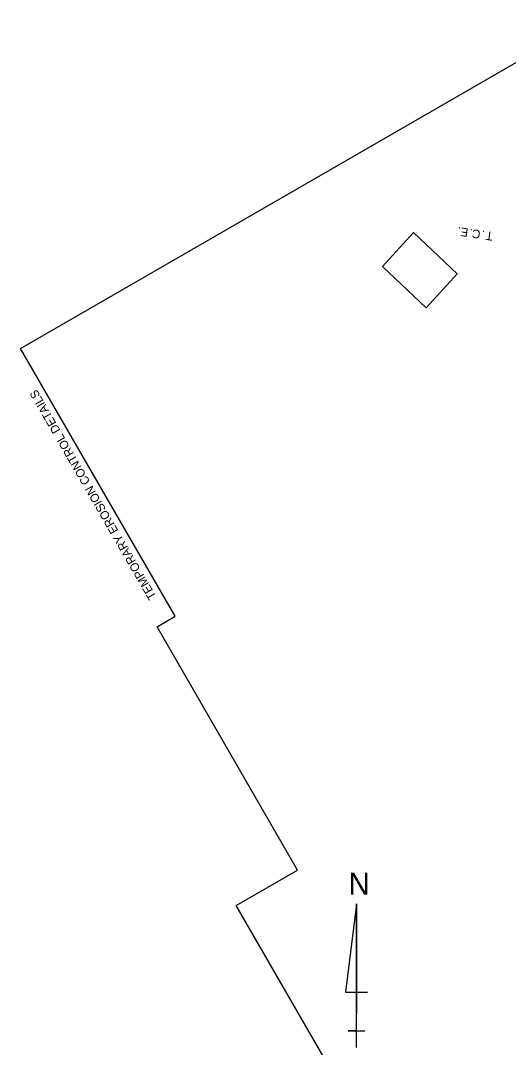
# Model space of a CAD drawing. Extents: x 956270 to 957915, y 1920230 to 1922423.
# Drawn here: x 956270 to 956610, y 1921447 to 1922163 of the extents above; entities that cross this region are included whole.
import ezdxf

# ---------------------------------------------------------------- set-up
doc = ezdxf.new("R2010")
doc.units = 0
for name, color, linetype in [('1', 7, 'Continuous'), ('63', 7, 'Continuous'), ('NO PLOT', 7, 'Continuous'), ('R_Draft', 7, 'Continuous')]:
    doc.layers.add(name, color=color, linetype=linetype)

msp = doc.modelspace()

# ---------------------------------------------------------------- linework, layer by layer
at = {"layer": '63'}
for p, q in [((956504.33, 1921547.02), (956496.64, 1921485.48)), ((956504.33, 1921447.02), (956504.33, 1921547.02)), ((956504.33, 1921547.02), (956504.33, 1921470.09)), ((956496.64, 1921485.48), (956512.03, 1921485.48)), ((956504.33, 1921447.02), (956504.33, 1921470.09)), ((956504.33, 1921458.55), (956498.57, 1921458.55)), ((956498.57, 1921458.55), (956510.1, 1921458.55)), ((956504.33, 1921447.02), (956504.33, 1921458.55))]:
    msp.add_line(p, q, dxfattribs=at)
at = {"layer": 'NO PLOT'}
for points in [[(957012.51, 1920520.44), (956420.48, 1921545.87), (956463.26, 1921570.57), (956365.36, 1921740.14), (956378, 1921747.44), (956270.25, 1921934.07), (956666.17, 1922162.65), (956816.66, 1921901.98), (956749.98, 1921863.48), (956962.48, 1921495.42), (957029.16, 1921533.92), (957172.25, 1921286.08), (957120.9, 1921256.43), (957292.23, 1920959.68), (957343.58, 1920989.33), (957463.85, 1920781.02)], [(957012.51, 1920520.44), (956420.48, 1921545.87), (956463.26, 1921570.57), (956365.36, 1921740.14), (956378, 1921747.44), (956270.25, 1921934.07), (956666.17, 1922162.65), (956816.66, 1921901.98), (956749.98, 1921863.48), (956962.48, 1921495.42), (957029.16, 1921533.92), (957172.25, 1921286.08), (957120.9, 1921256.43), (957292.23, 1920959.68), (957343.58, 1920989.33), (957463.85, 1920781.02)], [(957012.51, 1920520.44), (956420.48, 1921545.87), (956463.26, 1921570.57), (956365.36, 1921740.14), (956378, 1921747.44), (956270.25, 1921934.07), (956666.17, 1922162.65), (956816.66, 1921901.98), (956749.98, 1921863.48), (956962.48, 1921495.42), (957029.16, 1921533.92), (957172.25, 1921286.08), (957120.9, 1921256.43), (957292.23, 1920959.68), (957343.58, 1920989.33), (957463.85, 1920781.02)], [(957012.51, 1920520.44), (956420.48, 1921545.87), (956463.26, 1921570.57), (956365.36, 1921740.14), (956378, 1921747.44), (956270.25, 1921934.07), (956666.17, 1922162.65), (956816.66, 1921901.98), (956749.98, 1921863.48), (956962.48, 1921495.42), (957029.16, 1921533.92), (957172.25, 1921286.08), (957120.9, 1921256.43), (957292.23, 1920959.68), (957343.58, 1920989.33), (957463.85, 1920781.02)], [(957012.51, 1920520.44), (956420.48, 1921545.87), (956463.26, 1921570.57), (956365.36, 1921740.14), (956378, 1921747.44), (956270.25, 1921934.07), (956666.17, 1922162.65), (956816.66, 1921901.98), (956749.98, 1921863.48), (956962.48, 1921495.42), (957029.16, 1921533.92), (957172.25, 1921286.08), (957120.9, 1921256.43), (957292.23, 1920959.68), (957343.58, 1920989.33), (957463.85, 1920781.02)], [(956574.41, 1921986.06), (956552.79, 1921962.42), (956522.51, 1921991.32), (956544.13, 1922014.96)]]:
    msp.add_lwpolyline(points, close=True, dxfattribs=at)

# ---------------------------------------------------------------- texts
at = {"layer": '1'}
msp.add_text('TEMPORARY EROSION CONTROL DETAILS', height=6, rotation=120, dxfattribs=at).set_placement((956365.12, 1921761.15))
at = {"layer": '63'}
msp.add_text('N', height=15.38, rotation=360, dxfattribs=at).set_placement((956498.7, 1921553.43))
at = {"layer": 'R_Draft'}
for s, p in [('.', (956577.24, 1922018.5)), ('E', (956582.56, 1922017.69)), ('.', (956585.46, 1922017.25)), ('C', (956591.06, 1922016.4)), ('.', (956593.96, 1922015.97)), ('T', (956599.75, 1922015.09))]:
    msp.add_text(s, height=6, rotation=171.38948, dxfattribs=at).set_placement(p)

doc.saveas('drawing.dxf')
